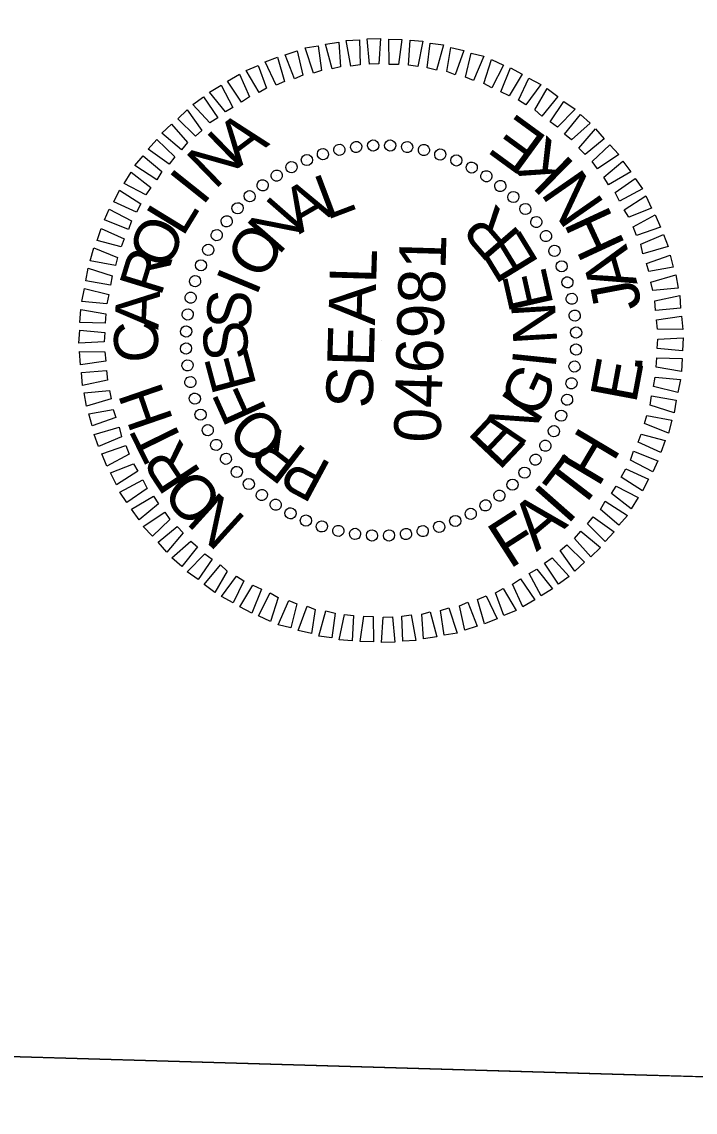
# Model space of a CAD drawing. Extents: x 2096999 to 2102576, y 682920 to 687015.
# Drawn here: x 2097153 to 2097239.6, y 686627 to 686767.1 of the extents above; entities that cross this region are included whole.
import ezdxf

# ---------------------------------------------------------------- set-up
doc = ezdxf.new("R2010")
doc.units = 0
for name, color, linetype in [('Default', 7, 'Continuous'), ('Old_Level_2', 7, 'Continuous'), ('Scratch_Level_2', 7, 'Continuous')]:
    doc.layers.add(name, color=color, linetype=linetype)

msp = doc.modelspace()

# ---------------------------------------------------------------- linework, layer by layer
at = {"layer": 'Default'}
for p, q in [((2097196.01, 686751.04), (2097196.01, 686751.04)), ((2097198.17, 686751.28), (2097198.17, 686751.28)), ((2097200.37, 686751.26), (2097200.37, 686751.26)), ((2097202.57, 686751.05), (2097202.57, 686751.05)), ((2097189.66, 686749.42), (2097189.66, 686749.42)), ((2097191.68, 686750.16), (2097191.68, 686750.16)), ((2097193.8, 686750.7), (2097193.8, 686750.7)), ((2097204.7, 686750.64), (2097204.7, 686750.64)), ((2097206.79, 686750.12), (2097206.79, 686750.12)), ((2097208.87, 686749.36), (2097208.87, 686749.36)), ((2097187.68, 686748.48), (2097187.68, 686748.48)), ((2097210.84, 686748.41), (2097210.84, 686748.41)), ((2097185.75, 686747.38), (2097185.75, 686747.38)), ((2097212.76, 686747.35), (2097212.76, 686747.35)), ((2097183.97, 686746.19), (2097183.97, 686746.19)), ((2097214.52, 686746.05), (2097214.52, 686746.05)), ((2097182.27, 686744.73), (2097182.27, 686744.73)), ((2097216.23, 686744.65), (2097216.23, 686744.65)), ((2097180.73, 686743.23), (2097180.73, 686743.23)), ((2097217.74, 686743.1), (2097217.74, 686743.1)), ((2097179.33, 686741.52), (2097179.33, 686741.52)), ((2097219.19, 686741.41), (2097219.19, 686741.41)), ((2097178.03, 686739.76), (2097178.03, 686739.76)), ((2097220.39, 686739.63), (2097220.39, 686739.63)), ((2097176.97, 686737.84), (2097176.97, 686737.84)), ((2097221.48, 686737.69), (2097221.48, 686737.69)), ((2097176.01, 686735.86), (2097176.01, 686735.86)), ((2097222.43, 686735.71), (2097222.43, 686735.71)), ((2097175.25, 686733.78), (2097175.25, 686733.78)), ((2097223.17, 686733.69), (2097223.17, 686733.69)), ((2097174.74, 686731.7), (2097174.74, 686731.7)), ((2097223.71, 686731.58), (2097223.71, 686731.58)), ((2097174.33, 686729.56), (2097174.33, 686729.56)), ((2097224.04, 686729.36), (2097224.04, 686729.36)), ((2097174.11, 686727.36), (2097174.11, 686727.36)), ((2097224.28, 686727.21), (2097224.28, 686727.21)), ((2097199.19, 686726.19), (2097199.19, 686726.19)), ((2097174.1, 686725.16), (2097174.1, 686725.16)), ((2097224.27, 686725.01), (2097224.27, 686725.01)), ((2097174.34, 686723.01), (2097174.34, 686723.01)), ((2097224.05, 686722.81), (2097224.05, 686722.81)), ((2097174.67, 686720.8), (2097174.67, 686720.8)), ((2097223.64, 686720.67), (2097223.64, 686720.67)), ((2097175.21, 686718.68), (2097175.21, 686718.68)), ((2097223.13, 686718.59), (2097223.13, 686718.59)), ((2097175.95, 686716.66), (2097175.95, 686716.66)), ((2097222.37, 686716.51), (2097222.37, 686716.51)), ((2097176.9, 686714.68), (2097176.9, 686714.68)), ((2097221.41, 686714.53), (2097221.41, 686714.53)), ((2097177.99, 686712.75), (2097177.99, 686712.75)), ((2097220.36, 686712.61), (2097220.36, 686712.61)), ((2097179.19, 686710.96), (2097179.19, 686710.96)), ((2097219.05, 686710.85), (2097219.05, 686710.85)), ((2097180.64, 686709.27), (2097180.64, 686709.27)), ((2097217.65, 686709.14), (2097217.65, 686709.14)), ((2097182.15, 686707.72), (2097182.15, 686707.72)), ((2097216.11, 686707.64), (2097216.11, 686707.64)), ((2097183.86, 686706.32), (2097183.86, 686706.32)), ((2097214.42, 686706.18), (2097214.42, 686706.18)), ((2097185.62, 686705.02), (2097185.62, 686705.02)), ((2097212.63, 686704.99), (2097212.63, 686704.99)), ((2097187.54, 686703.96), (2097187.54, 686703.96)), ((2097210.7, 686703.89), (2097210.7, 686703.89)), ((2097189.51, 686703.01), (2097189.51, 686703.01)), ((2097191.59, 686702.25), (2097191.59, 686702.25)), ((2097193.68, 686701.74), (2097193.68, 686701.74)), ((2097204.58, 686701.67), (2097204.58, 686701.67)), ((2097206.7, 686702.21), (2097206.7, 686702.21)), ((2097208.72, 686702.95), (2097208.72, 686702.95)), ((2097195.82, 686701.32), (2097195.82, 686701.32)), ((2097198.01, 686701.11), (2097198.01, 686701.11)), ((2097200.21, 686701.1), (2097200.21, 686701.1)), ((2097202.37, 686701.33), (2097202.37, 686701.33))]:
    msp.add_line(p, q, dxfattribs=at)
for points in [[(2097195.31, 686761.46), (2097194.71, 686764.73), (2097196.41, 686764.83), (2097196.52, 686761.63)], [(2097197.72, 686761.69), (2097197.42, 686764.95), (2097199.12, 686765), (2097198.92, 686761.76)], [(2097200.22, 686761.67), (2097200.17, 686764.92), (2097201.87, 686764.87), (2097201.42, 686761.64)], [(2097202.72, 686761.55), (2097202.91, 686764.79), (2097204.56, 686764.65), (2097203.92, 686761.41)], [(2097188.06, 686759.82), (2097186.85, 686762.91), (2097188.42, 686763.41), (2097189.13, 686760.29)], [(2097190.49, 686760.55), (2097189.43, 686763.78), (2097191.09, 686764.04), (2097191.55, 686760.87)], [(2097192.9, 686761.08), (2097192.04, 686764.26), (2097193.75, 686764.51), (2097193.96, 686761.35)], [(2097205.11, 686761.23), (2097205.5, 686764.42), (2097207.2, 686764.17), (2097206.3, 686760.94)], [(2097207.65, 686760.75), (2097208.14, 686763.84), (2097209.83, 686763.44), (2097208.69, 686760.32)], [(2097185.69, 686758.99), (2097184.28, 686761.98), (2097185.89, 686762.59), (2097186.8, 686759.46)], [(2097210.03, 686760.03), (2097210.77, 686763.11), (2097212.41, 686762.72), (2097211.07, 686759.6)], [(2097212.41, 686759.22), (2097213.4, 686762.29), (2097214.93, 686761.59), (2097213.44, 686758.64)], [(2097183.51, 686758.05), (2097181.84, 686760.9), (2097183.41, 686761.51), (2097184.48, 686758.63)], [(2097214.58, 686758.15), (2097215.82, 686761.22), (2097217.34, 686760.42), (2097215.66, 686757.62)], [(2097181.27, 686756.82), (2097179.45, 686759.52), (2097180.98, 686760.43), (2097182.29, 686757.49)], [(2097216.85, 686757.09), (2097218.18, 686759.9), (2097219.71, 686759.1), (2097217.78, 686756.46)], [(2097179.19, 686755.58), (2097177.16, 686758.09), (2097178.64, 686759), (2097180.15, 686756.15)], [(2097218.96, 686755.82), (2097220.54, 686758.58), (2097221.91, 686757.54), (2097219.84, 686755)], [(2097177.19, 686754.14), (2097175.01, 686756.5), (2097176.39, 686757.51), (2097178.21, 686754.81)], [(2097220.92, 686754.27), (2097222.69, 686756.92), (2097224.12, 686755.92), (2097221.85, 686753.59)], [(2097175.34, 686752.44), (2097173.06, 686754.66), (2097174.29, 686755.82), (2097176.17, 686753.17)], [(2097222.77, 686752.71), (2097224.8, 686755.25), (2097226.06, 686754.12), (2097223.65, 686751.99)], [(2097173.54, 686750.69), (2097171, 686752.82), (2097172.24, 686753.98), (2097174.32, 686751.62)], [(2097224.62, 686750.91), (2097226.74, 686753.4), (2097227.86, 686752.11), (2097225.4, 686750.08)], [(2097171.94, 686748.84), (2097169.24, 686750.77), (2097170.38, 686752.03), (2097172.67, 686749.77)], [(2097226.32, 686749.21), (2097228.58, 686751.34), (2097229.75, 686750.11), (2097226.99, 686748.24)], [(2097170.38, 686746.83), (2097167.53, 686748.66), (2097168.62, 686749.93), (2097171.01, 686747.91)], [(2097227.81, 686747.16), (2097230.27, 686749.24), (2097231.28, 686747.86), (2097228.43, 686746.19)], [(2097168.97, 686744.92), (2097166.16, 686746.35), (2097167.06, 686747.83), (2097169.6, 686745.85)], [(2097229.26, 686745.22), (2097231.86, 686746.99), (2097232.77, 686745.67), (2097229.82, 686744.1)], [(2097167.76, 686742.66), (2097164.84, 686743.99), (2097165.59, 686745.52), (2097168.34, 686743.74)], [(2097230.44, 686742.98), (2097233.2, 686744.76), (2097233.95, 686743.18), (2097231.01, 686742.02)], [(2097166.74, 686740.43), (2097163.63, 686741.68), (2097164.27, 686743.06), (2097167.12, 686741.57)], [(2097231.58, 686740.8), (2097234.42, 686742.32), (2097235.08, 686740.75), (2097232, 686739.69)], [(2097165.78, 686738.21), (2097162.7, 686739.05), (2097163.24, 686740.59), (2097166.16, 686739.25)], [(2097232.57, 686738.57), (2097235.5, 686739.79), (2097236.06, 686738.27), (2097232.83, 686737.31)], [(2097165.06, 686735.83), (2097161.82, 686736.43), (2097162.27, 686738.11), (2097165.34, 686736.87)], [(2097233.29, 686736.1), (2097236.33, 686737.16), (2097236.73, 686735.6), (2097233.61, 686735.04)], [(2097164.43, 686733.3), (2097161.25, 686733.84), (2097161.55, 686735.48), (2097164.62, 686734.49)], [(2097233.87, 686733.68), (2097237.05, 686734.64), (2097237.35, 686732.93), (2097234.09, 686732.62)], [(2097163.96, 686730.91), (2097160.72, 686731.21), (2097161.07, 686732.85), (2097164.2, 686732.1)], [(2097234.35, 686731.27), (2097237.58, 686731.97), (2097237.68, 686730.32), (2097234.47, 686730.06)], [(2097163.74, 686728.42), (2097160.49, 686728.51), (2097160.59, 686730.16), (2097163.83, 686729.61)], [(2097234.58, 686728.86), (2097237.8, 686729.31), (2097237.95, 686727.61), (2097234.7, 686727.65)], [(2097163.62, 686726.02), (2097160.37, 686725.86), (2097160.46, 686727.51), (2097163.71, 686727.22)], [(2097234.76, 686726.35), (2097238.02, 686726.51), (2097237.92, 686724.86), (2097234.68, 686725.15)], [(2097163.8, 686723.51), (2097160.58, 686723.06), (2097160.43, 686724.76), (2097163.68, 686724.72)], [(2097234.64, 686723.95), (2097237.89, 686723.86), (2097237.79, 686722.21), (2097234.56, 686722.76)], [(2097164.03, 686721.1), (2097160.81, 686720.4), (2097160.7, 686722.05), (2097163.91, 686722.31)], [(2097234.42, 686721.46), (2097237.66, 686721.17), (2097237.31, 686719.52), (2097234.18, 686720.27)], [(2097164.51, 686718.69), (2097161.33, 686717.73), (2097161.03, 686719.44), (2097164.29, 686719.75)], [(2097233.95, 686719.07), (2097237.13, 686718.53), (2097236.84, 686716.89), (2097233.76, 686717.88)], [(2097165.09, 686716.27), (2097162.06, 686715.21), (2097161.65, 686716.77), (2097164.77, 686717.33)], [(2097233.33, 686716.54), (2097236.56, 686715.95), (2097236.11, 686714.26), (2097233.04, 686715.5)], [(2097165.82, 686713.8), (2097162.88, 686712.58), (2097162.32, 686714.1), (2097165.55, 686715.06)], [(2097232.61, 686714.16), (2097235.68, 686713.32), (2097235.14, 686711.78), (2097232.23, 686713.12)], [(2097166.8, 686711.57), (2097163.96, 686710.05), (2097163.3, 686711.62), (2097166.38, 686712.68)], [(2097231.64, 686711.94), (2097234.76, 686710.7), (2097234.12, 686709.31), (2097231.26, 686710.8)], [(2097167.94, 686709.39), (2097165.19, 686707.62), (2097164.43, 686709.19), (2097167.37, 686710.35)], [(2097230.63, 686709.71), (2097233.54, 686708.38), (2097232.79, 686706.85), (2097230.04, 686708.63)], [(2097169.13, 686707.15), (2097166.52, 686705.38), (2097165.61, 686706.7), (2097168.56, 686708.27)], [(2097229.41, 686707.45), (2097232.22, 686706.02), (2097231.33, 686704.54), (2097228.78, 686706.52)], [(2097170.57, 686705.21), (2097168.11, 686703.13), (2097167.1, 686704.51), (2097169.95, 686706.18)], [(2097228, 686705.54), (2097230.85, 686703.71), (2097229.76, 686702.44), (2097227.37, 686704.46)], [(2097172.06, 686703.16), (2097169.8, 686701.03), (2097168.63, 686702.26), (2097171.39, 686704.13)], [(2097226.44, 686703.53), (2097229.14, 686701.6), (2097228, 686700.34), (2097225.72, 686702.6)], [(2097173.76, 686701.46), (2097171.64, 686698.97), (2097170.53, 686700.26), (2097172.99, 686702.29)], [(2097224.84, 686701.68), (2097227.38, 686699.56), (2097226.14, 686698.39), (2097224.06, 686700.75)], [(2097175.61, 686699.66), (2097173.59, 686697.12), (2097172.32, 686698.25), (2097174.73, 686700.39)], [(2097223.04, 686699.93), (2097225.32, 686697.71), (2097224.09, 686696.55), (2097222.22, 686699.2)], [(2097177.47, 686698.1), (2097175.69, 686695.46), (2097174.27, 686696.45), (2097176.54, 686698.78)], [(2097221.19, 686698.23), (2097223.37, 686695.87), (2097221.99, 686694.86), (2097220.17, 686697.56)], [(2097179.42, 686696.55), (2097177.84, 686693.79), (2097176.47, 686694.83), (2097178.55, 686697.37)], [(2097219.2, 686696.79), (2097221.22, 686694.28), (2097219.75, 686693.37), (2097218.23, 686696.22)], [(2097181.54, 686695.29), (2097180.2, 686692.47), (2097178.68, 686693.27), (2097180.6, 686695.91)], [(2097183.81, 686694.22), (2097182.57, 686691.15), (2097181.04, 686691.95), (2097182.72, 686694.75)], [(2097217.11, 686695.55), (2097218.93, 686692.85), (2097217.4, 686691.94), (2097216.09, 686694.88)], [(2097185.98, 686693.16), (2097184.99, 686690.08), (2097183.46, 686690.78), (2097184.94, 686693.74)], [(2097212.69, 686693.38), (2097214.11, 686690.39), (2097212.49, 686689.78), (2097211.58, 686692.91)], [(2097214.87, 686694.32), (2097216.54, 686691.47), (2097214.97, 686690.86), (2097213.9, 686693.74)], [(2097188.35, 686692.34), (2097187.61, 686689.26), (2097185.97, 686689.65), (2097187.32, 686692.77)], [(2097190.73, 686691.62), (2097190.24, 686688.53), (2097188.55, 686688.93), (2097189.7, 686692.05)], [(2097210.32, 686692.55), (2097211.53, 686689.46), (2097209.96, 686688.96), (2097209.25, 686692.08)], [(2097193.27, 686691.14), (2097192.88, 686687.95), (2097191.18, 686688.2), (2097192.08, 686691.43)], [(2097195.66, 686690.82), (2097195.47, 686687.58), (2097193.82, 686687.73), (2097194.47, 686690.96)], [(2097198.16, 686690.7), (2097198.22, 686687.45), (2097196.52, 686687.5), (2097196.96, 686690.74)], [(2097200.66, 686690.68), (2097200.97, 686687.42), (2097199.26, 686687.37), (2097199.46, 686690.61)], [(2097203.07, 686690.91), (2097203.67, 686687.64), (2097201.97, 686687.54), (2097201.86, 686690.74)], [(2097205.48, 686691.29), (2097206.34, 686688.11), (2097204.63, 686687.86), (2097204.42, 686691.02)], [(2097207.9, 686691.82), (2097208.95, 686688.59), (2097207.29, 686688.33), (2097206.84, 686691.5)]]:
    msp.add_lwpolyline(points, close=True, dxfattribs=at)
for centre, major_axis in [((2097191.72, 686750.13), (-0.215, 0.687)), ((2097193.83, 686750.69), (-0.154, 0.703)), ((2097195.99, 686751.06), (-0.092, 0.714)), ((2097198.17, 686751.24), (-0.029, 0.719)), ((2097200.36, 686751.24), (0.033, 0.719)), ((2097202.54, 686751.04), (0.096, 0.714)), ((2097204.69, 686750.66), (0.158, 0.702)), ((2097206.8, 686750.08), (0.218, 0.686)), ((2097189.66, 686749.38), (-0.274, 0.666)), ((2097208.86, 686749.33), (0.277, 0.664)), ((2097185.78, 686747.38), (-0.385, 0.608)), ((2097187.67, 686748.46), (-0.331, 0.64)), ((2097210.84, 686748.4), (0.334, 0.638)), ((2097212.73, 686747.3), (0.389, 0.606)), ((2097183.98, 686746.13), (-0.437, 0.572)), ((2097214.52, 686746.04), (0.44, 0.57)), ((2097182.3, 686744.73), (-0.485, 0.532)), ((2097216.19, 686744.63), (0.488, 0.529)), ((2097180.75, 686743.18), (-0.529, 0.488)), ((2097217.73, 686743.08), (0.532, 0.485)), ((2097179.34, 686741.51), (-0.57, 0.44)), ((2097219.13, 686741.4), (0.572, 0.437)), ((2097178.08, 686739.72), (-0.606, 0.389)), ((2097220.38, 686739.6), (0.608, 0.385)), ((2097176.98, 686737.83), (-0.638, 0.334)), ((2097221.47, 686737.7), (0.64, 0.331)), ((2097176.05, 686735.85), (-0.664, 0.277)), ((2097222.39, 686735.72), (0.666, 0.274)), ((2097175.29, 686733.8), (-0.686, 0.218)), ((2097223.13, 686733.66), (0.687, 0.215)), ((2097174.72, 686731.68), (-0.702, 0.158)), ((2097223.69, 686731.54), (0.703, 0.154)), ((2097174.34, 686729.53), (-0.714, 0.096)), ((2097224.07, 686729.39), (0.714, 0.092)), ((2097174.14, 686727.35), (-0.719, 0.033)), ((2097224.25, 686727.21), (0.719, 0.029)), ((2097174.13, 686725.16), (-0.719, -0.029)), ((2097224.24, 686725.02), (0.719, -0.033)), ((2097174.32, 686722.98), (-0.714, -0.092)), ((2097224.05, 686722.84), (0.714, -0.096)), ((2097174.69, 686720.83), (-0.703, -0.154)), ((2097223.66, 686720.69), (0.702, -0.158)), ((2097175.25, 686718.71), (-0.687, -0.215)), ((2097223.09, 686718.57), (0.686, -0.218)), ((2097175.99, 686716.65), (-0.666, -0.274)), ((2097222.33, 686716.52), (0.664, -0.277)), ((2097176.91, 686714.67), (-0.64, -0.331)), ((2097221.4, 686714.54), (0.638, -0.334)), ((2097178, 686712.77), (-0.608, -0.385)), ((2097220.3, 686712.65), (0.606, -0.389)), ((2097179.25, 686710.98), (-0.572, -0.437)), ((2097219.04, 686710.86), (0.57, -0.44)), ((2097180.65, 686709.29), (-0.532, -0.485)), ((2097217.63, 686709.19), (0.529, -0.488)), ((2097182.19, 686707.74), (-0.488, -0.529)), ((2097216.08, 686707.65), (0.485, -0.532)), ((2097183.87, 686706.33), (-0.44, -0.57)), ((2097185.65, 686705.07), (-0.389, -0.606)), ((2097214.4, 686706.24), (0.437, -0.572)), ((2097187.55, 686703.97), (-0.334, -0.638)), ((2097210.71, 686703.91), (0.331, -0.64)), ((2097212.61, 686704.99), (0.385, -0.608)), ((2097189.53, 686703.04), (-0.277, -0.664)), ((2097191.58, 686702.29), (-0.218, -0.686)), ((2097208.72, 686702.99), (0.274, -0.666)), ((2097193.69, 686701.72), (-0.158, -0.702)), ((2097195.85, 686701.33), (-0.096, -0.714)), ((2097198.02, 686701.13), (-0.033, -0.719)), ((2097200.21, 686701.13), (0.029, -0.719)), ((2097202.39, 686701.31), (0.092, -0.714)), ((2097204.55, 686701.68), (0.154, -0.703)), ((2097206.66, 686702.24), (0.215, -0.687))]:
    msp.add_ellipse(centre, major_axis=major_axis, ratio=0.999708, dxfattribs=at)
at = {"layer": 'Old_Level_2'}
msp.add_lwpolyline([(2097138.11, 686634.56), (2097143.57, 686821.42), (2097254.9, 686818.17), (2097249.44, 686631.3)], close=True, dxfattribs=at)
msp.add_lwpolyline([(2097138.11, 686634.56), (2097143.57, 686821.42), (2097254.9, 686818.17), (2097249.44, 686631.3)], close=True, dxfattribs=at)
at = {"layer": 'Scratch_Level_2'}
msp.add_lwpolyline([(2097234.32, 685317.78), (2097026.76, 685323.81), (2097058.72, 686423.24), (2097059.31, 686437.01), (2097065.14, 686636.69), (2097214.22, 686632.33), (2097231.8, 686631.82), (2097295.87, 686629.95), (2097298.79, 686729.78), (2098044.58, 686708.09), (2098037.23, 686456.47), (2098110.07, 686454.34), (2098090.85, 685704.42)], close=True, dxfattribs=at)

# ---------------------------------------------------------------- texts
at = {"layer": 'Default'}
for s, height, rotation, p in [('E', 6.14, 143.8279, (2097220.75, 686752.17)), ('A', 5.78, 36.952, (2097180.88, 686748.33)), ('N', 5.8, 44.1537, (2097177.84, 686745.46)), ('K', 6.16, 135.5439, (2097224.27, 686748.8)), ('I', 5.79, 51.355, (2097176.23, 686743.36)), ('N', 6.16, 124.8181, (2097228.04, 686743.73)), ('L', 5.71, 20.7357, (2097192.19, 686741.65)), ('A', 5.76, 30.0951, (2097188.68, 686739.8)), ('N', 5.8, 48.8114, (2097186, 686737.02)), ('R', 5.8, 130.8162, (2097217.34, 686739.76)), ('L', 5.77, 58.5557, (2097173.71, 686739.38)), ('H', 6.12, 114.8341, (2097230.64, 686738.47)), ('O', 5.73, 65.756, (2097171.74, 686735.04)), ('O', 5.77, 58.1683, (2097183.9, 686733.73)), ('E', 5.78, 121.4589, (2097219.59, 686736.15)), ('046981', 5.998, 88.3348, (2097206.82, 686712.99)), ('A', 6.06, 105.9938, (2097232.16, 686733.49)), ('R', 5.69, 72.9559, (2097170.89, 686731.71)), ('SEAL', 5.998, 88.3348, (2097198.09, 686717.41)), ('E', 5.68, 102.7466, (2097221.38, 686730.79)), ('I', 5.72, 67.5244, (2097183.15, 686731.75)), ('A', 5.64, 87.3551, (2097170.57, 686727.52)), ('J', 6.03, 100.736, (2097232.69, 686730.44)), ('S', 5.64, 86.2352, (2097182.32, 686727.48)), ('N', 5.64, 93.3912, (2097221.84, 686725.83)), ('C', 5.65, 94.5547, (2097170.75, 686723.56)), ('S', 5.65, 95.5904, (2097182.27, 686723.88)), ('E', 5.69, 104.9459, (2097183.22, 686720.4)), ('I', 5.64, 84.036, (2097221.59, 686722.48)), ('E', 6.02, 79.3925, (2097231.94, 686717.95)), ('.', 6, 86.5019, (2097232.7, 686722.07)), ('G', 5.73, 65.3251, (2097219.5, 686715.99)), ('H', 5.72, 108.9543, (2097172.53, 686715.91)), ('F', 5.75, 114.3019, (2097184.62, 686717.15)), ('N', 5.78, 55.9688, (2097217.14, 686712.26)), ('O', 5.8, 133.0161, (2097187.48, 686713.77)), ('E', 5.8, 46.6117, (2097214.36, 686709.34)), ('T', 5.76, 116.1546, (2097174.09, 686712.61)), ('R', 5.77, 142.3745, (2097189.87, 686711.95)), ('H', 6.13, 59.2082, (2097227.08, 686707.16)), ('R', 5.79, 123.3553, (2097176.19, 686709.15)), ('T', 6.16, 52.4079, (2097224.64, 686703.99)), ('P', 5.73, 151.7337, (2097193.03, 686710.26)), ('O', 5.8, 130.5566, (2097179.18, 686705.61)), ('I', 6.17, 48.606, (2097223.11, 686702.35)), ('N', 5.79, 137.7583, (2097182.02, 686703.22)), ('A', 6.16, 39.7657, (2097219.16, 686698.96)), ('F', 6.14, 32.7491, (2097215.69, 686696.73))]:
    msp.add_text(s, height=height, rotation=rotation, dxfattribs=at).set_placement(p)

doc.saveas('drawing.dxf')
